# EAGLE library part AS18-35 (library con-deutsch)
DEUTSCH Connector
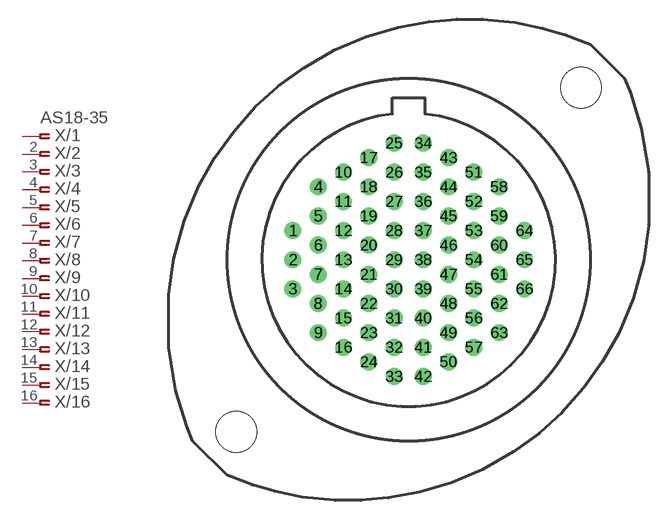
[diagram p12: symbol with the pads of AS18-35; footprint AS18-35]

Designator prefix X; gates /1=PINF_VAL /2=ASPINF /3=ASPINF /4=ASPINF /5=ASPINF /6=ASPINF /7=ASPINF /8=ASPINF /9=ASPINF /10=ASPINF /11=ASPINF /12=ASPINF /13=ASPINF /14=ASPINF /15=ASPINF /16=ASPINF /17=ASPINF /18=ASPINF /19=ASPINF /20=ASPINF /21=ASPINF /22=ASPINF /23=ASPINF /24=ASPINF /25=ASPINF /26=ASPINF /27=ASPINF /28=ASPINF /29=ASPINF /30=ASPINF /31=ASPINF /32=ASPINF /33=ASPINF /34=ASPINF /35=ASPINF /36=ASPINF /37=ASPINF /38=ASPINF /39=ASPINF /40=ASPINF /41=ASPINF /42=ASPINF /43=ASPINF /44=ASPINF /45=ASPINF /46=ASPINF /47=ASPINF /48=ASPINF /49=ASPINF /50=ASPINF /51=ASPINF /52=ASPINF /53=ASPINF /54=ASPINF /55=ASPINF /56=ASPINF /57=ASPINF /58=ASPINF /59=ASPINF /60=ASPINF /61=ASPINF /62=ASPINF /63=ASPINF /64=ASPINF /65=ASPINF /66=ASPINF

## AS18-35 (OC_FARNELL: unknown; OC_NEWARK: unknown)  [AS18-35]
1  /1:1  pas
2  /2:1  pas
3  /3:1  pas
4  /4:1  pas
5  /5:1  pas
6  /6:1  pas
7  /7:1  pas
8  /8:1  pas
9  /9:1  pas
10  /10:1  pas
11  /11:1  pas
12  /12:1  pas
13  /13:1  pas
14  /14:1  pas
15  /15:1  pas
16  /16:1  pas
17  /17:1  pas
18  /18:1  pas
19  /19:1  pas
20  /20:1  pas
21  /21:1  pas
22  /22:1  pas
23  /23:1  pas
24  /24:1  pas
25  /25:1  pas
26  /26:1  pas
27  /27:1  pas
28  /28:1  pas
29  /29:1  pas
30  /30:1  pas
31  /31:1  pas
32  /32:1  pas
33  /33:1  pas
34  /34:1  pas
35  /35:1  pas
36  /36:1  pas
37  /37:1  pas
38  /38:1  pas
39  /39:1  pas
40  /40:1  pas
41  /41:1  pas
42  /42:1  pas
43  /43:1  pas
44  /44:1  pas
45  /45:1  pas
46  /46:1  pas
47  /47:1  pas
48  /48:1  pas
49  /49:1  pas
50  /50:1  pas
51  /51:1  pas
52  /52:1  pas
53  /53:1  pas
54  /54:1  pas
55  /55:1  pas
56  /56:1  pas
57  /57:1  pas
58  /58:1  pas
59  /59:1  pas
60  /60:1  pas
61  /61:1  pas
62  /62:1  pas
63  /63:1  pas
64  /64:1  pas
65  /65:1  pas
66  /66:1  pas

## Footprint AS18-35 (pad centres in mm)
DEUTSCH Connector
drill 0.813 round: 1 -9.068,2.286; 2 -9.068,0; 3 -9.068,-2.286; 4 -7.087,5.715; 5 -7.087,3.429; 6 -7.087,1.143; 7 -7.087,-1.143; 8 -7.087,-3.429; 9 -7.087,-5.715; 10 -5.105,6.858; 11 -5.105,4.572; 12 -5.105,2.286; 13 -5.105,0; 14 -5.105,-2.286; 15 -5.105,-4.572; 16 -5.105,-6.858; 17 -3.124,8.001; 18 -3.124,5.715; 19 -3.124,3.429; 20 -3.124,1.143; 21 -3.124,-1.143; 22 -3.124,-3.429; 23 -3.124,-5.715; 24 -3.124,-8.001; 25 -1.143,9.144; 26 -1.143,6.858; 27 -1.143,4.572; 28 -1.143,2.286; 29 -1.143,0; 30 -1.143,-2.286; 31 -1.143,-4.572; 32 -1.143,-6.858; 33 -1.143,-9.144; 34 1.143,9.144; 35 1.143,6.858; 36 1.143,4.572; 37 1.143,2.286; 38 1.143,0; 39 1.143,-2.286; 40 1.143,-4.572; 41 1.143,-6.858; 42 1.143,-9.144; 43 3.124,8.001; 44 3.124,5.715; 45 3.124,3.429; 46 3.124,1.143; 47 3.124,-1.143; 48 3.124,-3.429; 49 3.124,-5.715; 50 3.124,-8.001; 51 5.105,6.858; 52 5.105,4.572; 53 5.105,2.286; 54 5.105,0; 55 5.105,-2.286; 56 5.105,-4.572; 57 5.105,-6.858; 58 7.087,5.715; 59 7.087,3.429; 60 7.087,1.143; 61 7.087,-1.143; 62 7.087,-3.429; 63 7.087,-5.715; 64 9.068,2.286; 65 9.068,0; 66 9.068,-2.286
hole 3.2 at -13.49,-13.49
hole 3.2 at 13.49,13.49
